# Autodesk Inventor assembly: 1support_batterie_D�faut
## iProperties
Created: 2011-01
Part Number: 1support_batterie_D�faut
Document SubType Name: Assembly
Designer: eric
Mass: 42.3789 g
Surface Area: 218.745 cm^2
Volume: 42.3789 cm^3
Density: 1 g/cm^3
Author: eric
